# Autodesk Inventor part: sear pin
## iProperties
Created: 2006-04
Part Number: sear pin
Document SubType Name: Modeling
Designer: Калинин
Author: Калинин
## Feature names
1. Вращение1 [Revolution]
2. Фаска1 [Chamfer]
3. Вращение2 [Revolution]
4. Вращение3 [Revolution]
5. Разделение1
6. Разделение2
7. Сопряжение1 [Fillet]
